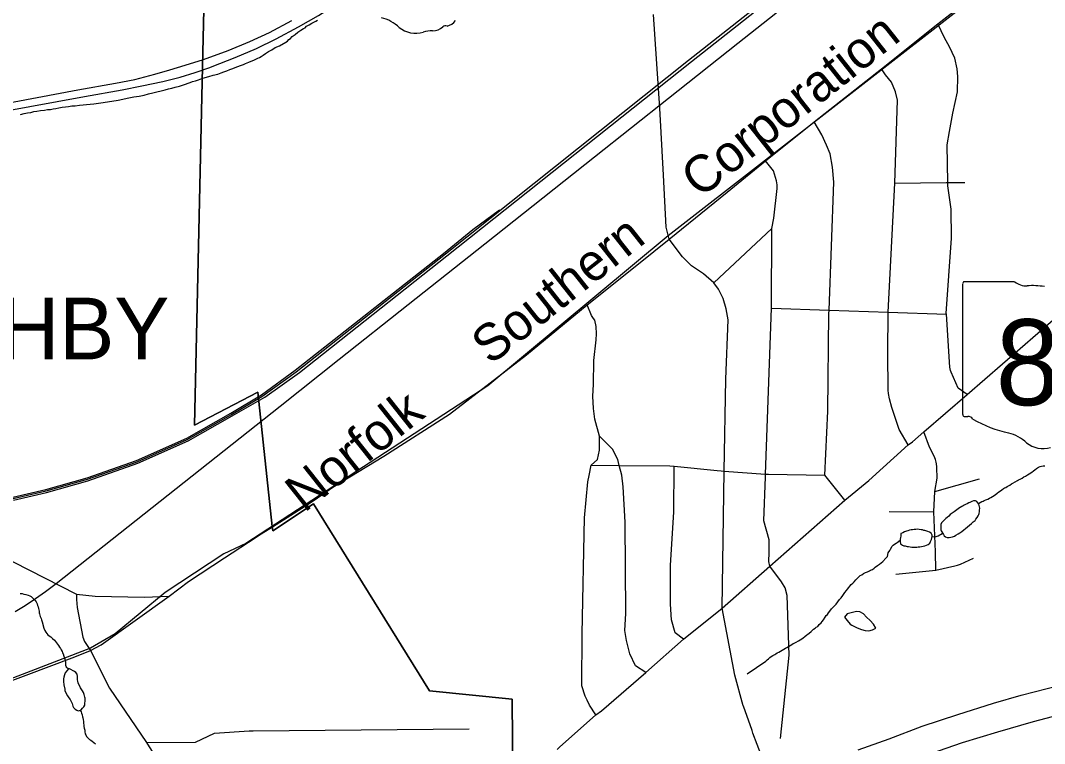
# Model space of a CAD drawing. Extents: x 0 to 34, y 0 to 22.
# Drawn here: x 6.635 to 8.206, y 14.779 to 15.889 of the extents above; entities that cross this region are included whole.
import ezdxf

# ---------------------------------------------------------------- set-up
doc = ezdxf.new("R2010")
doc.units = 0
for name, color, linetype in [('GM_X_City_Street', 7, 'Continuous'), ('GM_X_Corporation', 7, 'Continuous'), ('GM_X_Corporation_Text', 7, 'Continuous'), ('GM_X_County_Road', 7, 'Continuous'), ('GM_X_Interstate_Route', 7, 'Continuous'), ('GM_X_Minor_Lake', 7, 'Continuous'), ('GM_X_Minor_River', 7, 'Continuous'), ('GM_X_Rail_Line', 7, 'Continuous'), ('GM_X_Rail_Line_Text', 7, 'Continuous'), ('GM_X_State_Location', 7, 'Continuous'), ('GM_X_State_Route', 7, 'Continuous'), ('GM_X_State_Shield', 7, 'Continuous'), ('GM_X_US_Route', 7, 'Continuous')]:
    doc.layers.add(name, color=color, linetype=linetype)

msp = doc.modelspace()

# ---------------------------------------------------------------- linework, layer by layer
at = {"layer": 'GM_X_City_Street'}
for p, q in [((8.0578, 15.6405), (8.0841, 15.6407)), ((7.699, 15.4863), (7.7879, 15.5698)), ((8.0379, 15.1664), (8.1062, 15.1859)), ((7.9677, 15.1353), (8.0364, 15.1349))]:
    msp.add_line(p, q, dxfattribs=at)
for points in [[(8.0874, 15.3152), (8.0737, 15.3249), (8.0628, 15.3493), (8.062, 15.3519), (8.0613, 15.3547), (8.061, 15.3569), (8.0556, 15.4382), (8.0555, 15.4393), (8.0635, 15.555), (8.0631, 15.5995), (8.0579, 15.6352), (8.0578, 15.6405), (8.0566, 15.6985), (8.0602, 15.7187), (8.0655, 15.747), (8.0726, 15.7796), (8.0731, 15.8032), (8.0724, 15.815), (8.0685, 15.8312), (8.0604, 15.8489), (8.0528, 15.8628), (8.0427, 15.884)], [(7.997, 15.2378), (7.9834, 15.2612), (7.9718, 15.2951), (7.9682, 15.3085), (7.9669, 15.3164), (7.9665, 15.3216), (7.9657, 15.3787), (7.9665, 15.4413), (7.9766, 15.6397), (7.9808, 15.7668), (7.9776, 15.7798), (7.9715, 15.7944), (7.9624, 15.8057), (7.9559, 15.8151)], [(7.8996, 15.153), (7.8693, 15.1912), (7.8738, 15.2894), (7.8754, 15.4388), (7.8756, 15.4444), (7.8828, 15.6408), (7.881, 15.664), (7.8773, 15.6843), (7.8715, 15.6979), (7.8647, 15.7138), (7.8527, 15.7338)], [(7.8012, 14.7872), (7.8146, 14.915), (7.8115, 15.0068), (7.8085, 15.0185), (7.8028, 15.0276), (7.7849, 15.0518), (7.7831, 15.0586), (7.7838, 15.0725), (7.7838, 15.0918), (7.7756, 15.1214), (7.7781, 15.1885), (7.7782, 15.1929), (7.7874, 15.4474), (7.7879, 15.5698), (7.7909, 15.5857), (7.7962, 15.6315), (7.796, 15.6334), (7.796, 15.6369), (7.795, 15.6429), (7.7903, 15.6586), (7.7783, 15.6736)], [(7.9766, 15.6397), (8.0553, 15.6405), (8.0578, 15.6405)], [(7.5946, 14.8886), (7.5784, 14.8987), (7.57, 14.9169), (7.5649, 14.9374), (7.5625, 14.9529), (7.5638, 14.9791), (7.5629, 15.1193), (7.5599, 15.1736), (7.5579, 15.1911), (7.5538, 15.2063), (7.5514, 15.2155), (7.5436, 15.2312), (7.5236, 15.2512), (7.516, 15.2772), (7.5143, 15.2938), (7.5131, 15.3127), (7.514, 15.3306), (7.5145, 15.3674), (7.5181, 15.399), (7.5189, 15.4084), (7.5183, 15.4195), (7.516, 15.429), (7.5143, 15.432), (7.5112, 15.4365), (7.5045, 15.4529)], [(7.7874, 15.4474), (7.8756, 15.4444), (7.9665, 15.4413), (8.0556, 15.4382)], [(8.0396, 15.0453), (8.0387, 15.0738), (8.0364, 15.1349), (8.0379, 15.1664), (8.0414, 15.1865), (8.0417, 15.1903), (8.0411, 15.1996), (8.0408, 15.2041), (8.0403, 15.2086), (8.04, 15.2113), (8.0387, 15.2154), (8.0367, 15.2206), (8.0298, 15.2342), (8.0208, 15.2579)], [(7.5178, 14.8233), (7.5083, 14.8385), (7.5043, 14.8457), (7.5014, 14.8521), (7.4962, 14.868), (7.4968, 14.9476), (7.5006, 15.1257), (7.5055, 15.1812), (7.5077, 15.1907), (7.5107, 15.2067), (7.5201, 15.2155), (7.5234, 15.2296), (7.5236, 15.2512)], [(7.5107, 15.2067), (7.5538, 15.2063), (7.6315, 15.2055), (7.6378, 15.2049), (7.7041, 15.1983), (7.7099, 15.1978), (7.7148, 15.1974), (7.7782, 15.1929), (7.7825, 15.1926), (7.8693, 15.1912)], [(7.6523, 14.9395), (7.6397, 14.9492), (7.6338, 14.9693), (7.6325, 14.9933), (7.6321, 15.0529), (7.6373, 15.1346), (7.6378, 15.2049)], [(7.9781, 15.0394), (8.0396, 15.0453), (8.0686, 15.0521), (8.0728, 15.0534), (8.0773, 15.0549), (8.0972, 15.0639)], [(6.7208, 15.0088), (6.7495, 15.0054), (6.8248, 15.0039), (6.863, 15.0056)], [(6.8285, 14.7811), (6.9036, 14.7816), (6.9328, 14.7951), (6.9859, 14.7988), (6.9918, 14.7989), (7.3235, 14.8019)]]:
    msp.add_lwpolyline(points, dxfattribs=at)
at = {"layer": 'GM_X_Corporation'}
for points in [[(6.9579, 18.132), (6.9502, 17.5872), (6.9468, 17.2888), (6.9413, 17.0038), (6.9287, 16.435), (6.9142, 15.8181), (6.9021, 15.2678), (6.9994, 15.3186), (7.0214, 15.1124), (7.0221, 15.106), (7.0848, 15.1475), (7.2625, 14.8601), (7.3892, 14.8475), (7.3905, 14.7219), (7.3907, 14.701), (7.7494, 14.7173), (7.8563, 14.7146), (7.8592, 14.6786), (7.9049, 14.6645), (8.8347, 14.6937), (8.9001, 14.6961), (8.9001, 19.9513)], [(7.3905, 14.7219), (7.3892, 14.8475), (7.2625, 14.8601), (7.0848, 15.1475), (7.0221, 15.106), (7.0214, 15.1124), (6.9994, 15.3186), (6.9021, 15.2678), (6.9142, 15.8181), (6.9287, 16.435), (6.9413, 17.0038), (6.9468, 17.2888), (6.9502, 17.5872), (6.9579, 18.132)]]:
    msp.add_lwpolyline(points, dxfattribs=at)
at = {"layer": 'GM_X_County_Road'}
msp.add_line((6.5949, 15.0728), (6.7208, 15.0088), dxfattribs=at)
for points in [[(6.7208, 15.0088), (6.721, 15.0005), (6.7222, 14.9884), (6.7305, 14.9428), (6.7334, 14.9361), (6.7426, 14.922)], [(6.7426, 14.922), (6.7716, 14.8644), (6.8285, 14.7811), (6.8301, 14.7786), (6.8736, 14.7096), (6.8879, 14.6955), (6.9139, 14.6797), (6.9659, 14.6487)]]:
    msp.add_lwpolyline(points, dxfattribs=at)
at = {"layer": 'GM_X_Interstate_Route'}
for points in [[(7.9205, 14.7695), (7.9678, 14.7868), (8.0184, 14.8059), (8.073, 14.8241), (8.1279, 14.8414), (8.1706, 14.8535), (8.2301, 14.869), (8.281, 14.8809), (8.383, 14.9014), (8.6062, 14.9451), (8.8651, 14.996), (8.9001, 15.0028)], [(7.873, 14.7025), (7.9366, 14.729), (8.0198, 14.7601), (8.0806, 14.781), (8.1348, 14.7973), (8.1895, 14.813), (8.2377, 14.8261), (8.2893, 14.8384), (8.3875, 14.8584), (8.6106, 14.9021), (8.8639, 14.9516), (8.9001, 14.9587)]]:
    msp.add_lwpolyline(points, dxfattribs=at)
at = {"layer": 'GM_X_Minor_Lake'}
for points in [[(8.0476, 15.1061), (8.0512, 15.1001), (8.0523, 15.0982), (8.0543, 15.0964), (8.0566, 15.0957), (8.0597, 15.0954), (8.0627, 15.0962), (8.065, 15.0966), (8.068, 15.0979), (8.0702, 15.0991), (8.0736, 15.101), (8.0762, 15.1026), (8.0792, 15.105), (8.0822, 15.1074), (8.0848, 15.1093), (8.0882, 15.1121), (8.0912, 15.1144), (8.0942, 15.1172), (8.0968, 15.1195), (8.0997, 15.1219), (8.1008, 15.1238), (8.1031, 15.1262), (8.1045, 15.1289), (8.1052, 15.1308), (8.1059, 15.1327), (8.1063, 15.1354), (8.1066, 15.1377), (8.1069, 15.1404), (8.1052, 15.1468), (8.104, 15.1487), (8.1024, 15.1509), (8.1001, 15.152), (8.0974, 15.1519), (8.0948, 15.1511), (8.0918, 15.1495), (8.0899, 15.1487), (8.0877, 15.1475), (8.085, 15.1463), (8.0831, 15.1451), (8.0813, 15.1443), (8.0794, 15.1431), (8.0768, 15.1415), (8.0757, 15.141)], [(8.0757, 15.141), (8.0674, 15.1352), (8.0644, 15.1328), (8.0614, 15.1308), (8.0592, 15.1285), (8.0566, 15.1265), (8.0547, 15.1246), (8.0525, 15.1226), (8.0506, 15.1206), (8.048, 15.1183), (8.0473, 15.1156), (8.047, 15.1126), (8.0471, 15.1107), (8.0472, 15.1068), (8.0476, 15.1061)], [(7.986, 15.1019), (7.986, 15.1), (7.9857, 15.0977), (7.9854, 15.0954), (7.9847, 15.0931), (7.9848, 15.0896), (7.9852, 15.0858), (7.9883, 15.084), (7.9906, 15.0829), (7.9926, 15.0826), (7.9956, 15.0819), (7.9975, 15.0816), (8.0002, 15.0813), (8.0025, 15.081), (8.0059, 15.081), (8.0086, 15.0807), (8.0105, 15.0808), (8.0124, 15.0812), (8.0151, 15.0813), (8.0173, 15.0817), (8.0227, 15.0826), (8.0249, 15.0838), (8.0275, 15.085), (8.0302, 15.087), (8.0312, 15.0893), (8.0327, 15.0924), (8.0337, 15.097), (8.0337, 15.0993), (8.0321, 15.1023), (8.0297, 15.1037), (8.027, 15.1048), (8.0228, 15.1062), (8.0209, 15.1066), (8.019, 15.1073), (8.0167, 15.1076), (8.0167, 15.1076)], [(8.0167, 15.1076), (8.011, 15.1082), (8.0087, 15.1078), (8.006, 15.1077), (8.0037, 15.1076), (8.0018, 15.1072), (7.9988, 15.1068), (7.9965, 15.1059), (7.9943, 15.1055), (7.9916, 15.1043), (7.989, 15.1027), (7.9864, 15.1019), (7.9864, 15.1019), (7.986, 15.1019)], [(7.9036, 14.9787), (7.8995, 14.9733), (7.9033, 14.968), (7.9079, 14.9628), (7.9106, 14.9611)], [(7.9475, 14.9567), (7.9436, 14.9624), (7.9386, 14.968), (7.9333, 14.9733), (7.9287, 14.9785), (7.9229, 14.9815), (7.9176, 14.9819), (7.9036, 14.9787)], [(7.9106, 14.9611), (7.919, 14.9572), (7.9255, 14.9546), (7.9308, 14.9531), (7.9365, 14.9524), (7.9422, 14.954), (7.9475, 14.9567)], [(6.71, 14.8941), (6.7085, 14.8938), (6.7059, 14.8911), (6.7037, 14.8877), (6.7026, 14.885), (6.7015, 14.8812), (6.7011, 14.8785), (6.7012, 14.8755), (6.7012, 14.8736), (6.7016, 14.8705), (6.7017, 14.8694)], [(6.7017, 14.8694), (6.7028, 14.8626), (6.7032, 14.8607), (6.704, 14.858), (6.7071, 14.8527), (6.7094, 14.8497), (6.711, 14.847), (6.7129, 14.844), (6.7141, 14.8406), (6.7149, 14.8387), (6.7153, 14.8368), (6.7164, 14.8345), (6.7187, 14.8319), (6.7214, 14.8304), (6.7233, 14.8297), (6.7256, 14.8301), (6.7282, 14.8309), (6.7301, 14.8339), (6.732, 14.8358), (6.7335, 14.8381), (6.7338, 14.8412), (6.7342, 14.8442), (6.7341, 14.8465), (6.7341, 14.8488), (6.7337, 14.8507), (6.7333, 14.8526), (6.7329, 14.8545), (6.7317, 14.8579), (6.7302, 14.8605), (6.7283, 14.8632), (6.7271, 14.8651), (6.7236, 14.8723), (6.7228, 14.8749), (6.7224, 14.8772), (6.7227, 14.8802), (6.7227, 14.8825), (6.7219, 14.8856), (6.72, 14.8882), (6.7177, 14.8897), (6.71, 14.8941)]]:
    msp.add_lwpolyline(points, dxfattribs=at)
at = {"layer": 'GM_X_Minor_River'}
for points in [[(6.9472, 15.8105), (6.9518, 15.8121), (6.9563, 15.814), (6.9608, 15.8156), (6.9642, 15.8171), (6.9684, 15.8187), (6.9725, 15.8202), (6.9771, 15.8218), (6.9805, 15.8234), (6.9854, 15.8253), (6.9892, 15.8265), (6.9929, 15.8281), (6.9963, 15.8296), (6.999, 15.8312), (7.0016, 15.8323), (7.0043, 15.8339), (7.0073, 15.8358), (7.011, 15.8385), (7.0156, 15.8416), (7.0209, 15.8443), (7.0257, 15.8478), (7.0322, 15.8505), (7.042, 15.8559), (7.0446, 15.8575), (7.0469, 15.8598), (7.0491, 15.8617), (7.0521, 15.8648), (7.0563, 15.8679), (7.0604, 15.8713), (7.0649, 15.8744), (7.0694, 15.8771), (7.0717, 15.8779), (7.074, 15.8806), (7.0781, 15.8825), (7.0819, 15.8849), (7.0853, 15.8868), (7.0883, 15.8883), (7.0906, 15.8895)], [(6.6348, 15.745), (6.6405, 15.7462), (6.6458, 15.7474), (6.6511, 15.7482), (6.6553, 15.7494), (6.6602, 15.7502), (6.6655, 15.751), (6.6716, 15.7515), (6.6765, 15.7523), (6.681, 15.7527), (6.6852, 15.7535), (6.6894, 15.7543), (6.6939, 15.7551), (6.6988, 15.7559), (6.7041, 15.7567), (6.7087, 15.7571), (6.7136, 15.758), (6.7189, 15.7584), (6.7257, 15.7592), (6.7311, 15.7597), (6.7364, 15.7601), (6.7417, 15.7605), (6.7477, 15.7613), (6.7549, 15.7622), (6.7621, 15.7634), (6.7849, 15.767), (6.7921, 15.7682), (6.7989, 15.7702), (6.8091, 15.7718), (6.8171, 15.7731), (6.8246, 15.7747), (6.8314, 15.7766), (6.8379, 15.7782), (6.8443, 15.7798), (6.8508, 15.781), (6.8568, 15.7826), (6.8621, 15.7842), (6.8674, 15.7854), (6.8723, 15.7869), (6.8791, 15.7885), (6.8837, 15.7901), (6.8882, 15.7916), (6.8924, 15.7928), (6.8954, 15.794), (6.8988, 15.7956), (6.9033, 15.7967), (6.9083, 15.7983), (6.9132, 15.7999), (6.9185, 15.8015), (6.9241, 15.803), (6.9306, 15.8054), (6.9378, 15.807), (6.9427, 15.8089), (6.9472, 15.8105)], [(8.1047, 15.1476), (8.1101, 15.1507), (8.1119, 15.1515), (8.1138, 15.1523), (8.1161, 15.1535), (8.1191, 15.1547), (8.1217, 15.156), (8.124, 15.1572), (8.1266, 15.1584), (8.1304, 15.1611), (8.1333, 15.1635), (8.136, 15.1655), (8.1386, 15.1674), (8.1408, 15.169), (8.1431, 15.1706), (8.1449, 15.1718), (8.1468, 15.1726), (8.1487, 15.1738), (8.151, 15.175), (8.1528, 15.1762), (8.1558, 15.1782), (8.1577, 15.179), (8.1611, 15.1809), (8.1645, 15.1829), (8.1663, 15.1841), (8.169, 15.1853), (8.172, 15.1869), (8.1746, 15.1885), (8.1772, 15.1897), (8.1802, 15.1917), (8.1829, 15.1933), (8.1866, 15.1961), (8.1892, 15.1977), (8.1915, 15.1996), (8.1941, 15.2016), (8.1971, 15.2036), (8.1997, 15.2048), (8.2016, 15.2052), (8.2043, 15.2057), (8.2069, 15.2057)], [(8.0337, 15.0969), (8.0372, 15.0967), (8.0402, 15.0971), (8.0432, 15.0984), (8.0458, 15.0996), (8.0477, 15.1008), (8.0498, 15.1024)], [(7.7501, 14.8862), (7.7788, 14.9058), (7.7807, 14.9078), (7.7829, 14.9094), (7.7848, 14.9113), (7.787, 14.9129), (7.7893, 14.9145), (7.7923, 14.9161), (7.7941, 14.9173), (7.796, 14.9184), (7.7986, 14.9197), (7.8013, 14.9212), (7.8035, 14.9228), (7.8061, 14.9244), (7.8088, 14.9256), (7.8107, 14.9268), (7.8133, 14.9284), (7.8159, 14.93), (7.8185, 14.9316), (7.8204, 14.9328), (7.8223, 14.9332), (7.8249, 14.9348), (7.8287, 14.9368), (7.8339, 14.94), (7.8358, 14.9415), (7.8384, 14.9435), (7.8414, 14.9463), (7.8433, 14.9474), (7.8451, 14.949), (7.8481, 14.9514), (7.8515, 14.9549), (7.8541, 14.9565), (7.8559, 14.958), (7.8582, 14.9592), (7.8604, 14.962), (7.8634, 14.9647), (7.8652, 14.9667), (7.8671, 14.9694), (7.8697, 14.9732), (7.8711, 14.9759), (7.873, 14.9775), (7.8748, 14.9798), (7.877, 14.9826), (7.8796, 14.9861), (7.8815, 14.9884), (7.8833, 14.9903), (7.8863, 14.9935), (7.8889, 14.997), (7.8918, 15.0005), (7.894, 15.0032), (7.8966, 15.0067), (7.8999, 15.0113), (7.9025, 15.0144), (7.904, 15.0164), (7.9062, 15.0191), (7.9077, 15.021), (7.9095, 15.0234), (7.9121, 15.0257), (7.9144, 15.0277), (7.9166, 15.0304), (7.9188, 15.0328), (7.9214, 15.0351), (7.9236, 15.0371), (7.9259, 15.0383), (7.9285, 15.0402), (7.9315, 15.0418), (7.9345, 15.0431), (7.9375, 15.0443), (7.9394, 15.0455), (7.9421, 15.0467), (7.9447, 15.0486), (7.9465, 15.0502), (7.9499, 15.0526), (7.9529, 15.0549), (7.9555, 15.0565), (7.9581, 15.0589), (7.9629, 15.064), (7.9652, 15.0667), (7.9665, 15.072), (7.9687, 15.0759), (7.9698, 15.0778), (7.9724, 15.0825), (7.9742, 15.084), (7.9761, 15.0856), (7.9784, 15.0868), (7.9802, 15.088), (7.9847, 15.0914)], [(6.6347, 15.0098), (6.6374, 15.0095), (6.6401, 15.0084), (6.6431, 15.008), (6.6469, 15.0069), (6.6492, 15.0062), (6.6515, 15.005), (6.6534, 15.0028), (6.6557, 15.0009), (6.6576, 14.999), (6.6592, 14.9971), (6.6607, 14.9937), (6.6611, 14.9915), (6.6619, 14.9892), (6.6627, 14.9865), (6.6631, 14.9846), (6.6635, 14.9827), (6.6639, 14.9801), (6.6643, 14.9782), (6.6647, 14.9763), (6.6651, 14.9744), (6.6667, 14.9714), (6.6675, 14.9695), (6.6683, 14.966)], [(6.6683, 14.966), (6.671, 14.9562), (6.6726, 14.9528), (6.6737, 14.9505), (6.6753, 14.9482), (6.6772, 14.9464), (6.6791, 14.9449), (6.6818, 14.943), (6.6841, 14.9407), (6.6872, 14.9381), (6.6887, 14.9362), (6.6903, 14.9339), (6.6918, 14.932), (6.6933, 14.9298), (6.6949, 14.9275), (6.6964, 14.9252), (6.6972, 14.9234), (6.6988, 14.9207), (6.6995, 14.9188), (6.7003, 14.9169), (6.7015, 14.9135), (6.7027, 14.9105), (6.7035, 14.9074), (6.7043, 14.9044), (6.7043, 14.9025), (6.7043, 14.8998), (6.7051, 14.8972), (6.7085, 14.8938)], [(6.7266, 14.8304), (6.7279, 14.8278), (6.7287, 14.8259), (6.7295, 14.8233), (6.7302, 14.8206), (6.7307, 14.8187), (6.7311, 14.8161), (6.7315, 14.813), (6.7319, 14.81), (6.7323, 14.8081), (6.7323, 14.8054), (6.7327, 14.8028), (6.7335, 14.8001), (6.7339, 14.7971), (6.7343, 14.7944), (6.7351, 14.7925), (6.7363, 14.7902), (6.7378, 14.7884), (6.7409, 14.7857), (6.7428, 14.7846), (6.7451, 14.7831), (6.7478, 14.7809), (6.7501, 14.779)]]:
    msp.add_lwpolyline(points, dxfattribs=at)
at = {"layer": 'GM_X_Rail_Line'}
for points in [[(6.6237, 15.1553), (6.6743, 15.1672), (6.7378, 15.1849), (6.814, 15.2116), (6.891, 15.2462), (6.9588, 15.2844), (7.0054, 15.3121), (7.0582, 15.3501), (7.2871, 15.5311), (7.6599, 15.8282), (8.0769, 16.1566), (8.5157, 16.5045), (8.8904, 16.7977), (8.9001, 16.8054)], [(6.6242, 15.153), (6.6748, 15.1649), (6.7385, 15.1827), (6.8148, 15.2095), (6.8921, 15.2442), (6.96, 15.2825), (7.0098, 15.3111), (7.0632, 15.3489), (7.289, 15.5277), (7.6646, 15.8264), (8.083, 16.1569), (8.5171, 16.5027), (8.8918, 16.7959), (8.9001, 16.8025)], [(6.6266, 14.9819), (6.6396, 14.9896), (6.6528, 14.9982), (6.6734, 15.0126), (6.6898, 15.0251), (7.0335, 15.2973), (7.1242, 15.3694), (7.23, 15.4532), (7.3475, 15.5463), (7.4216, 15.6051), (7.5158, 15.6797), (7.6294, 15.7697), (7.7359, 15.8545), (8.0929, 16.1372), (8.3833, 16.3675), (8.7147, 16.6305), (8.9001, 16.7773)], [(8.9001, 16.2761), (8.2846, 16.0525), (8.2351, 16.0308), (7.6286, 15.5585), (7.3522, 15.3285), (6.9809, 15.0864), (6.9468, 15.0706), (6.8568, 15.011), (6.7801, 14.9477), (6.7423, 14.9258), (6.4831, 14.826), (6.4161, 14.8066), (6.3197, 14.7585), (6.2075, 14.6898), (6.1801, 14.6771), (6.15, 14.6743), (6.1143, 14.6764), (6.1057, 14.6241), (6.068, 14.5413), (6.0488, 14.5029)], [(6.6233, 15.1575), (6.6737, 15.1694), (6.7371, 15.1871), (6.8131, 15.2138), (6.89, 15.2483), (6.9575, 15.2864), (7.0046, 15.3145), (7.0566, 15.3526), (7.2838, 15.5315), (7.3291, 15.5683), (7.37, 15.5985)]]:
    msp.add_lwpolyline(points, dxfattribs=at)
at = {"layer": 'GM_X_State_Route'}
for points in [[(6.9254, 15.8172), (6.9293, 15.8185), (6.9642, 15.8326), (6.9969, 15.8462), (7.0274, 15.8608), (7.0616, 15.8793), (7.0924, 15.897), (7.1268, 15.9189), (7.1549, 15.9384), (7.1785, 15.9571), (7.198, 15.9734), (7.2182, 15.9909), (7.2437, 16.0148), (7.311, 16.0857), (7.3604, 16.1376), (7.4183, 16.2007), (7.5413, 16.3341)], [(6.5624, 15.7523), (6.723, 15.7826), (6.7807, 15.7928), (6.8107, 15.7987), (6.8413, 15.807), (6.8639, 15.8135), (6.8875, 15.8205), (6.9157, 15.8295), (6.9535, 15.8433), (6.9871, 15.8569), (7.017, 15.8708), (7.0512, 15.8892)], [(7.6215, 15.652), (7.6159, 15.7546), (7.6065, 15.8986)], [(7.7115, 14.9873), (7.7849, 15.0518), (7.8996, 15.153), (7.9364, 15.1832), (7.997, 15.2378), (8.0037, 15.2425), (8.0208, 15.2579), (8.0874, 15.3152), (8.2772, 15.4796), (8.4913, 15.667), (8.6494, 15.8039), (8.7321, 15.8767)], [(6.0172, 15.5686), (6.0458, 15.5871), (6.0753, 15.6041), (6.1061, 15.6213), (6.1247, 15.6298), (6.1629, 15.6475), (6.1946, 15.6601), (6.2414, 15.6756), (6.2772, 15.6867), (6.3106, 15.6951), (6.3484, 15.703), (6.4011, 15.7126), (6.4757, 15.7246), (6.565, 15.7419), (6.7334, 15.7726), (6.7911, 15.7828), (6.8211, 15.7888), (6.8534, 15.7955), (6.8799, 15.8022), (6.9031, 15.8095), (6.9254, 15.8172)], [(7.6304, 15.5536), (7.6258, 15.572), (7.6215, 15.652)], [(7.7115, 14.9873), (7.7148, 15.1974), (7.717, 15.3388), (7.721, 15.4296), (7.7177, 15.4468), (7.7129, 15.4623), (7.7061, 15.4769), (7.699, 15.4863), (7.6831, 15.5005), (7.6647, 15.5125), (7.6509, 15.5262), (7.6304, 15.5536)], [(7.4582, 14.7703), (7.4619, 14.7736), (7.5178, 14.8233), (7.5267, 14.8298), (7.5946, 14.8886), (7.6523, 14.9395), (7.7115, 14.9873)], [(7.744, 14.8375), (7.7308, 14.8842), (7.7115, 14.9873)], [(7.7574, 14.7993), (7.7442, 14.8365), (7.744, 14.8375)], [(7.7719, 14.7606), (7.7588, 14.7955), (7.7574, 14.7993)]]:
    msp.add_lwpolyline(points, dxfattribs=at)
at = {"layer": 'GM_X_State_Shield'}
for p, q in [((8.0806, 15.4847), (8.0806, 15.2846)), ((8.1604, 15.4882), (8.0832, 15.4882))]:
    msp.add_line(p, q, dxfattribs=at)
for centre, radius, start, end in [((7.1733, 15.8322), 0.0632, 47.1842, 75.836), ((7.2845, 15.9027), 0.0226, 282.8732, 323.2771), ((7.2416, 15.9096), 0.0401, 230.7004, 286.2918), ((7.2648, 15.8404), 0.0329, 85.6951, 111.2099), ((7.2677, 15.8946), 0.0214, 268.777, 315.5493), ((7.287, 15.8752), 0.00601, 65.7517, 132.6484), ((8.0836, 15.4852), 0.00305, 98.1301, 188.1301), ((8.1788, 15.5114), 0.0296, 231.6195, 271.1119), ((8.1886, 15.3758), 0.1064, 80.4867, 94.9883), ((8.0837, 15.2842), 0.00308, 171.9584, 258.3066), ((8.0841, 15.3046), 0.0235, 267.339, 280.6039), ((8.0889, 15.2731), 0.00848, 29.7484, 93.2717), ((8.196, 15.4529), 0.2019, 240.4129, 257.1985), ((8.1358, 15.1947), 0.0632, 47.1842, 75.836), ((8.2041, 15.2721), 0.0401, 230.7004, 286.2918)]:
    msp.add_arc(centre, radius, start, end, dxfattribs=at)
at = {"layer": 'GM_X_US_Route'}
for p, q in [((7.6304, 15.5536), (7.7191, 15.6256)), ((7.5832, 15.5158), (7.6304, 15.5536))]:
    msp.add_line(p, q, dxfattribs=at)
for points in [[(7.7191, 15.6256), (7.7783, 15.6736), (7.8527, 15.7338), (7.9559, 15.8151), (8.0427, 15.884), (8.1736, 15.9862), (8.1837, 15.9943)], [(7.1055, 15.1667), (7.1145, 15.173), (7.1925, 15.2203), (7.2935, 15.285), (7.4113, 15.3762), (7.5045, 15.4529), (7.5832, 15.5158)], [(7.0723, 15.1442), (7.0825, 15.1507), (7.1055, 15.1667)], [(7.0044, 15.1011), (7.0216, 15.1118), (7.0723, 15.1442)], [(6.5664, 14.8555), (6.5683, 14.8562), (6.7185, 14.9123), (6.7426, 14.922), (6.7587, 14.9307), (6.863, 15.0056), (6.8928, 15.0283), (6.9478, 15.0646), (6.9967, 15.0963), (7.0044, 15.1011)]]:
    msp.add_lwpolyline(points, dxfattribs=at)

# ---------------------------------------------------------------- texts
at = {"layer": 'GM_X_Corporation_Text'}
msp.add_text('WILLOUGHBY', height=0.0947, rotation=0, dxfattribs=at).set_placement((6.019, 15.369))
at = {"layer": 'GM_X_Rail_Line_Text'}
for s, height, rotation, p in [('Corporation', 0.056629, 38.2943, (7.6776, 15.6151)), ('Southern', 0.05663, 38.3763, (7.356, 15.3591)), ('Norfolk', 0.05663, 38.4568, (7.0705, 15.1327))]:
    msp.add_text(s, height=height, rotation=rotation, dxfattribs=at).set_placement(p)
at = {"layer": 'GM_X_State_Location'}
msp.add_text('84', height=0.000189, rotation=0, dxfattribs=at).set_placement((8.1618, 15.3576))
at = {"layer": 'GM_X_State_Shield'}
msp.add_text('84', height=0.13184, dxfattribs=at).set_placement((8.1312, 15.2987))

doc.saveas('drawing.dxf')
